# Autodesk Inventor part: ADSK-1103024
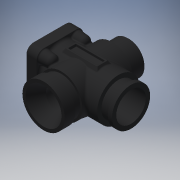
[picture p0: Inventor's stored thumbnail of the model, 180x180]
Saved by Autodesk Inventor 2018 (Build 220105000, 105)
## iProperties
Shininess: 11.0
Length Units: 11272
Angle Units: 11279
Time Units: 11290
Mass Units: 11286
Length Display Precision: 4
Angle Display Precision: 2
Compacted: True
Created: 2000-08
Part Number: ADSK-1103024
Document SubType Name: Modeling
Description: CARB HOUSING
Mass: 7.38977 g
Surface Area: 30.8 cm^2
Volume: 2.72685 cm^3
Density: 2.71 g/cm^3
Material: Aluminum-6061
Appearance: Black
Density: 0.0
Volumn: 0.0
Area: 0.0
PropertySet Name: Model Information
Control State: 0
Master: False
Checked Out: False
Author: Autodesk, Inc.
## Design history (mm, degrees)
node "Extrusion1" dims "d1" = 15.24, "d2" = 0
  sketch "Sketch3"
    geometry: C1 r 6.35 at (6.191, -11.43)
    constraints: 1 centre point
    dimensions: "d0" = 12.7 diameter of C1
workaxis "Work Axis1"
workplane "Work Plane1"
node "Extrusion2" dims "d5" = 19.05, "d6" = 0
  sketch "Sketch4"
    geometry: L1 (-6.35, 15.24)-(6.35, 15.24) reference; L2 (0, -3.048)-(0, 18.288) reference; C1 r 6.35 at (0, 7.62)
    constraints: 1 centre point, 1 midpoint
    dimensions: "d4" = 12.7 diameter of C1; "d23" = 1.27 distance edge to line of C1 L1
node "Extrusion3" dims "d8" = 2.0955, "d9" = 0
  sketch "Sketch5"
    geometry: C1 r 5.715 at (6.191, -11.43); A1 r 6.35 centre (6.191, -11.43) between (12.541, -11.43) and (-0.159, -11.43) reference
    constraints: 1 centre point, 1 coincident
    dimensions: "d7" = 0.635 radial gap between concentric circles of A1 C1
node "Extrusion4" dims "d10" = 3.175, "d11" = 0
  sketch "Sketch6"
    geometry: A1 r 6.35 centre (0, 0) between (6.35, 0) and (-6.35, 0) reference; A2 r 6.35 centre (0, 0) between (-6.35, 0) and (6.35, 0) reference
node "Extrusion5" dims "d13" = 3.175, "d14" = 0
  sketch "Sketch7"
    geometry: L1 (-6.985, 6.985)-(6.985, 6.985); L2 (6.985, 6.985)-(6.985, -6.985); L3 (6.985, -6.985)-(-6.985, -6.985); L4 (-6.985, -6.985)-(-6.985, 6.985); C1 r 6.35 at (0, 0) reference; C2 r 6.985 at (0, 0)
    constraints: 8 end point, 4 tangent, 2 parallel, 1 centre point, 1 coincident, 1 horizontal, 1 perpendicular
    dimensions: "d12" = 0.635 radial gap between concentric circles of C1 C2
node "Fillet1" dims "d15" = 2.0955
workaxis "Work Axis2"
workplane "Work Plane2"
node "Revolution1" dims "d17" = 90 deg
  sketch "Sketch8"
    geometry: L1 (-13.652, 0)-(15.24, 0) reference; L2 (-9.525, -6.35)-(0, -6.35) reference; L3 (0, -6.35)-(7.938, -6.35) reference; L4 (-1.675, -4.053)-(-3.549, -6.35); L5 (-3.549, -6.35)-(1.623, -10.571); L6 (1.623, -10.571)-(3.498, -8.274); L7 (3.498, -8.274)-(-1.675, -4.053)
    constraints: 8 end point, 2 parallel, 1 perpendicular, 1 point on line
node "Extrusion6" dims "d19" = 3.175, "d20" = 0
  sketch "Sketch9"
    geometry: C1 r 3.599 at (0, 0); A1 r 2.964 centre (0, 0) between (-2.964, 0) and (2.964, 0); A2 r 2.964 centre (0, 0) between (-1.31, 2.659) and (1.31, 2.659) reference
    constraints: 2 centre point, 2 point on circle, 1 coincident, 1 concentric
    dimensions: "d18" = 0.635 radial gap between concentric circles of C1 A1
node "Fillet4" dims "d24" = 0.8128
node "Fillet5" dims "d25" = 0.8128
node "Fillet16" dims "d78" = 0.8128
node "Fillet17" dims "d79" = 0.8128
node "Fillet18" dims "d80" = 0.381
node "Extrusion12" dims "d50" = 5.08, "d51" = 0
  sketch "Sketch16"
    geometry: C1 r 6.35 at (0, 0) reference; C2 r 5.006 at (0, 0)
    constraints: 1 centre point, 1 coincident
node "Hole1" dims "d28" = 6.35, "d29" = 10.795, "d30" = 6.35, "d31" = 60 deg, "d32" = 19.05, "d33" = 118 deg
  sketch "Sketch10"
    geometry: C1 r 6.35 at (0, 0) reference
node "Extrusion7" dims "d35" = 0.635, "d36" = 0
  sketch "Sketch11"
    geometry: C1 r 6.35 at (0, 0) reference; C2 r 4.445 at (0, 0)
    constraints: 1 centre point, 1 coincident
    dimensions: "d81" = 8.89 diameter of C2
node "Extrusion8" dims "d38" = 0.635, "d39" = 0
  sketch "Sketch12"
    geometry: C1 r 1.048 at (0, 0); A1 r 1.531 centre (0, 0) between (-1.514, 0.226) and (1.514, 0.226); A2 r 2.583 centre (0, 0) between (-2.16, 1.416) and (2.16, 1.416) reference; A3 r 2.787 centre (0, 0) between (0.61, 2.719) and (-0.61, 2.719) reference; 4 further points
    constraints: 2 centre point, 2 coincident, 2 point on circle, 5 other
    dimensions: "d37" = 2.0955 diameter of C1
node "Extrusion9" dims "d41" = 1.27, "d42" = 0
  sketch "Sketch13"
    geometry: C1 r 4.445 at (0, 0) reference; C2 r 2.349 at (0, 0)
    constraints: 1 centre point, 1 coincident
    dimensions: "d40" = 2.0955 radial gap between concentric circles of C1 C2
node "Extrusion10" dims "d43" = 0, "d44" = 2.54
  sketch "Sketch14"
    geometry: C1 r 5.08 at (6.191, -11.112); C2 r 6.35 at (6.191, -11.112) reference; 2 further points
    constraints: 1 centre point, 1 concentric, 2 other
    dimensions: "d46" = 1.27 radial gap between concentric circles of C2 C1
node "Extrusion11" dims "d47" = 1.27, "d48" = 0
  sketch "Sketch15"
    geometry: C1 r 4.445 at (0, 0) reference; C2 r 5.715 at (0, 0); C3 r 5.08 at (0, 0) reference
    constraints: 1 centre point, 1 concentric
    dimensions: "d49" = 0.635 radial gap between concentric circles of C2 C3
node "Chamfer1" dims "d52" = 0.381, "d53" = 0.381, "d82" = 45 deg
node "Extrusion13" dims "d58" = 1.27, "d59" = 30 deg
  sketch "Sketch17"
    geometry: L1 (6.35, -3.302)-(15.875, -3.302); L2 (15.875, -3.302)-(15.875, -6.477); L3 (15.875, -6.477)-(6.35, -6.477); L4 (6.35, -6.477)-(6.35, -3.302); L5 (24.765, -4.889)-(-4.128, -4.889) reference; L6 (11.113, 12.929)-(11.113, -22.898) reference
    constraints: 8 end point, 2 parallel, 1 horizontal, 1 perpendicular
    dimensions: "d54" = 3.175 distance of L1.end L2.end; "d55" = 9.525 distance of L2.end L3.end; "d56" = 4.7625 distance between parallel lines of L6 L2 (= 0.5 x d55); "d57" = 1.5875 distance between parallel lines of L1 L5 (= 0.5 x d54)
node "Fillet8" dims "d60" = 0.381
node "Fillet9" dims "d61" = 0.381
node "Extrusion14" dims "d62" = 0.762, "d63" = 0
  sketch "Sketch18"
    geometry: L1 (6.79, -3.742)-(15.435, -3.742); L2 (15.435, -3.742)-(15.435, -6.037); L3 (15.435, -6.037)-(6.79, -6.037); L4 (6.79, -6.037)-(6.79, -3.742); 4 further points; 2 other entities
    constraints: 8 end point, 2 parallel, 1 horizontal, 1 perpendicular, 2 other
node "Fillet10" dims "d64" = 0.127
node "Extrusion15" dims "d71" = 6.731, "d72" = -5 deg
  sketch "Sketch20"
    geometry: A1 r 2.096 centre (4.889, 4.889) between (6.985, 4.889) and (4.889, 6.985) reference; A2 r 2.096 centre (-4.889, 4.889) between (-4.889, 6.985) and (-6.985, 4.889) reference; A3 r 2.096 centre (-4.889, -4.889) between (-6.985, -4.889) and (-4.889, -6.985) reference; A4 r 2.095 centre (4.889, -4.889) between (4.889, -6.985) and (6.985, -4.889) reference; 4 further points
    constraints: 4 coincident, 3 vertical alignment, 1 horizontal alignment, 8 other
node "Hole2" dims "d65" = 2.013, "d66" = 9.525, "d67" = 6.35, "d68" = 60 deg, "d69" = 5.08, "d70" = 118 deg
  sketch "Sketch19"
    geometry: A1 r 2.095 centre (4.889, -4.889) between (4.889, -6.985) and (6.985, -4.889) reference; A2 r 2.096 centre (4.889, 4.889) between (6.985, 4.889) and (4.889, 6.985) reference; A3 r 2.096 centre (-4.889, 4.889) between (-4.889, 6.985) and (-6.985, 4.889) reference; A4 r 2.096 centre (-4.889, -4.889) between (-6.985, -4.889) and (-4.889, -6.985) reference
node "Fillet11" dims "d73" = 0.127
node "Fillet12" dims "d74" = 1.27
node "Fillet14" dims "d76" = 0.381
node "Fillet15" dims "d77" = 0.381
body "Solid1"
other parameters: "d3" = 90 deg, "d16" = 0
